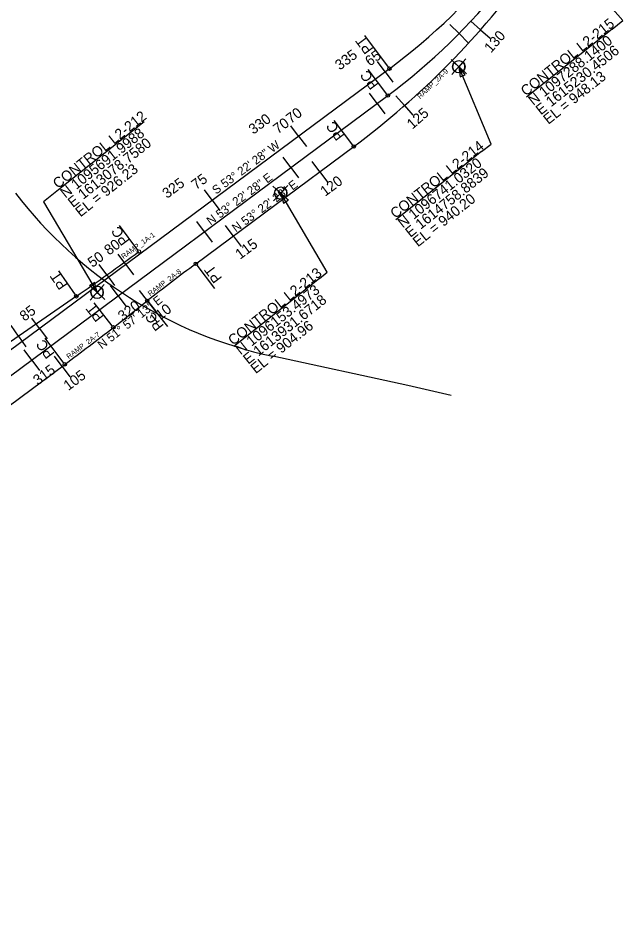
# Model space of a CAD drawing. Extents: x 1603447 to 1622636, y 1083818 to 1103958.
# Drawn here: x 1612712 to 1615521, y 1092765 to 1096967 of the extents above; entities that cross this region are included whole.
import ezdxf

# ---------------------------------------------------------------- set-up
doc = ezdxf.new("R2010")
doc.units = 0
for name, color, linetype in [('Level 1', 7, 'Continuous'), ('RD_HC_Points', 7, 'Continuous'), ('RD_HC_SUR_Bearing_TX400', 7, 'Continuous'), ('RD_HC_SUR_CL400', 7, 'Continuous'), ('RD_HC_SUR_PC_PT_400', 7, 'Continuous'), ('RD_HC_SUR_Tic400', 7, 'Continuous'), ('RD_HC_SUR_TX_Sta400', 7, 'Continuous'), ('RD_SHT_Misc1', 7, 'Continuous'), ('RD_TX_Misc1', 7, 'Continuous')]:
    doc.layers.add(name, color=color, linetype=linetype)

msp = doc.modelspace()

# ---------------------------------------------------------------- linework, layer by layer
at = {"layer": 'RD_HC_Points'}
for p, q in [((1615470.7, 1096915.2), (1615072.9, 1096598.8)), ((1613297.3, 1096484.8), (1612899.4, 1096168.3)), ((1614865, 1096346.2), (1614466.8, 1096029.4)), ((1614111.4, 1095756.1), (1613713.5, 1095439.7))]:
    msp.add_line(p, q, dxfattribs=at)
for points in [[(1615470.7, 1096915.2), (1615521.2, 1096955.3), (1615230.5, 1097288.1)], [(1614865, 1096346.2), (1614908.9, 1096381.1), (1614758.9, 1096741)], [(1612899.4, 1096168.3), (1612830.5, 1096113.5), (1613078.8, 1095692)], [(1614111.4, 1095756.1), (1614148.1, 1095785.3), (1613931.7, 1096153.5)]]:
    msp.add_lwpolyline(points, dxfattribs=at)
for points in [[(1614788.2, 1096703), (1614758.9, 1096741), (1614765.3, 1096693.5)], [(1613965.9, 1096119.8), (1613931.7, 1096153.5), (1613944.5, 1096107.2)], [(1613044.5, 1095725.6), (1613078.8, 1095692), (1613065.9, 1095738.3)]]:
    msp.add_lwpolyline(points, close=True, dxfattribs=at)
at = {"layer": 'RD_HC_SUR_CL400'}
for p, q in [((1614436.6, 1096731.7), (1611265.2, 1094374.2)), ((1609261, 1092765), (1614429, 1096606.7)), ((1613537.5, 1095824.7), (1614270.8, 1096369.8)), ((1612982.5, 1095673.6), (1612407.5, 1095277.3)), ((1613154.3, 1095529.3), (1613311.8, 1095652.5)), ((1614522.1, 1095259), (1613894.5, 1095394.8)), ((1612190.2, 1094808.2), (1612928.5, 1095357.1)), ((1614723.1, 1095212.2), (1614522.1, 1095259))]:
    msp.add_line(p, q, dxfattribs=at)
for centre, radius, start, end in [((1612727.4, 1099031), 2865, 306.6256, 336.8024), ((1612720.8, 1098904.6), 2863.3, 306.6256, 336.8024), ((1612003.8, 1099419.5), 3800, 306.6256, 324.318), ((1614328.1, 1097398.4), 2050, 217.402, 257.7882), ((1607307.2, 1103907.2), 10000, 304.57794, 306.62559), ((1620368.4, 1086635.5), 11450, 126.62559, 128.04643), ((1606097.7, 1104546.3), 11450, 306.62559, 308.04643)]:
    msp.add_arc(centre, radius, start, end, dxfattribs=at)
at = {"layer": 'RD_HC_SUR_PC_PT_400'}
for p, q in [((1614431.8, 1096738.1), (1614321.8, 1096886.1)), ((1614424.2, 1096613.1), (1614338.5, 1096728.5)), ((1614266.1, 1096376.2), (1614180.3, 1096491.6)), ((1613268.3, 1095888.1), (1613182.5, 1096003.5)), ((1613542.3, 1095818.3), (1613623.4, 1095709.3)), ((1612977.9, 1095680.2), (1612900.8, 1095792)), ((1613316.7, 1095646.2), (1613405.3, 1095533)), ((1613149.4, 1095535.6), (1613065.6, 1095642.5)), ((1612923.8, 1095363.5), (1612838, 1095478.9))]:
    msp.add_line(p, q, dxfattribs=at)
for centre in [(1614436.6, 1096731.7), (1614429, 1096606.7), (1614270.8, 1096369.8), (1613273, 1095881.7), (1613537.5, 1095824.7), (1612982.5, 1095673.6), (1613311.8, 1095652.5), (1613154.3, 1095529.3), (1612928.5, 1095357.1)]:
    msp.add_circle(centre, 8, dxfattribs=at)
at = {"layer": 'RD_HC_SUR_Tic400'}
for p, q in [((1614860.1, 1096913.2), (1614815, 1096952.8)), ((1614760.1, 1096894.7), (1614717.3, 1096936.8)), ((1614860.1, 1096913.2), (1614905.2, 1096873.6)), ((1614648.8, 1096905.8), (1614648.8, 1096905.8)), ((1614760.1, 1096894.7), (1614802.8, 1096852.6)), ((1614573.5, 1096840.1), (1614573.5, 1096840.1)), ((1614688.6, 1096824.7), (1614688.6, 1096824.7)), ((1614793.2, 1096838.9), (1614793.2, 1096838.9)), ((1614416.3, 1096716.5), (1614380.5, 1096764.7)), ((1614495.9, 1096777), (1614495.9, 1096777)), ((1614614.8, 1096757.3), (1614614.8, 1096757.3)), ((1614724.3, 1096766.4), (1614724.3, 1096766.4)), ((1614416.3, 1096716.5), (1614452, 1096668.4)), ((1614336, 1096656.9), (1614336, 1096656.9)), ((1614538.7, 1096692.4), (1614538.7, 1096692.4)), ((1614653.5, 1096695.7), (1614653.5, 1096695.7)), ((1614380.2, 1096570.4), (1614344.4, 1096618.6)), ((1614460.3, 1096630.3), (1614460.3, 1096630.3)), ((1614581, 1096627), (1614581, 1096627)), ((1614255.7, 1096597.2), (1614255.7, 1096597.2)), ((1614380.2, 1096570.4), (1614416, 1096522.3)), ((1614506.6, 1096560.1), (1614467.1, 1096605.3)), ((1614175.5, 1096537.6), (1614175.5, 1096537.6)), ((1614506.6, 1096560.1), (1614546.1, 1096515)), ((1614300, 1096510.8), (1614300, 1096510.8)), ((1614430.5, 1096495.3), (1614430.5, 1096495.3)), ((1614015, 1096418.2), (1613979.2, 1096466.4)), ((1614095.2, 1096477.9), (1614095.2, 1096477.9)), ((1614219.7, 1096451.1), (1614219.7, 1096451.1)), ((1614015, 1096418.2), (1614050.8, 1096370.1)), ((1614352.7, 1096432.4), (1614352.7, 1096432.4)), ((1614273.3, 1096371.6), (1614273.3, 1096371.6)), ((1613934.7, 1096358.6), (1613934.7, 1096358.6)), ((1613978.9, 1096272.1), (1613943.1, 1096320.3)), ((1614059.2, 1096331.8), (1614059.2, 1096331.8)), ((1613854.5, 1096298.9), (1613854.5, 1096298.9)), ((1614112.8, 1096252.3), (1614077, 1096300.5)), ((1614193, 1096312), (1614193, 1096312)), ((1613774.2, 1096239.3), (1613774.2, 1096239.3)), ((1613978.9, 1096272.1), (1614014.7, 1096224)), ((1614112.8, 1096252.3), (1614148.6, 1096204.2)), ((1613898.7, 1096212.5), (1613898.7, 1096212.5)), ((1614032.5, 1096192.7), (1614032.5, 1096192.7)), ((1613613.7, 1096119.9), (1613577.9, 1096168.1)), ((1613694, 1096179.6), (1613694, 1096179.6)), ((1613818.4, 1096152.8), (1613818.4, 1096152.8)), ((1613613.7, 1096119.9), (1613649.5, 1096071.8)), ((1613952.3, 1096133), (1613952.3, 1096133)), ((1613738.2, 1096093.2), (1613738.2, 1096093.2)), ((1613872, 1096073.3), (1613872, 1096073.3)), ((1613533.4, 1096060.3), (1613533.4, 1096060.3)), ((1613657.9, 1096033.5), (1613657.9, 1096033.5)), ((1613453.2, 1096000.6), (1613453.2, 1096000.6)), ((1613577.7, 1095973.8), (1613541.9, 1096022)), ((1613711.5, 1095954), (1613675.7, 1096002.2)), ((1613791.8, 1096013.7), (1613791.8, 1096013.7)), ((1613372.9, 1095941), (1613372.9, 1095941)), ((1613577.7, 1095973.8), (1613613.5, 1095925.7)), ((1613711.5, 1095954), (1613747.3, 1095905.9)), ((1613497.4, 1095914.2), (1613497.4, 1095914.2)), ((1613212.4, 1095821.7), (1613176.6, 1095869.8)), ((1613292.7, 1095881.3), (1613292.7, 1095881.3)), ((1613631.2, 1095894.4), (1613631.2, 1095894.4)), ((1613123.9, 1095772.9), (1613089, 1095821.7)), ((1613204.9, 1095831.5), (1613204.9, 1095831.5)), ((1613212.4, 1095821.7), (1613248.2, 1095773.5)), ((1613417.2, 1095854.5), (1613417.2, 1095854.5)), ((1613551, 1095834.7), (1613551, 1095834.7)), ((1613123.9, 1095772.9), (1613158.8, 1095724.1)), ((1613336.9, 1095794.9), (1613336.9, 1095794.9)), ((1613470.9, 1095774.8), (1613470.9, 1095774.8)), ((1613132.2, 1095762), (1613132.2, 1095762)), ((1613256.6, 1095735.2), (1613256.6, 1095735.2)), ((1613042.3, 1095715.2), (1613042.3, 1095715.2)), ((1613051.9, 1095702.3), (1613051.9, 1095702.3)), ((1613176.4, 1095675.6), (1613140.6, 1095723.7)), ((1613312.3, 1095652.9), (1613275.4, 1095700.2)), ((1613391.4, 1095714.2), (1613391.4, 1095714.2)), ((1612960.1, 1095658.2), (1612960.1, 1095658.2)), ((1613176.4, 1095675.6), (1613212.2, 1095627.4)), ((1613312.3, 1095652.9), (1613349.3, 1095605.7)), ((1612971.7, 1095642.7), (1612971.7, 1095642.7)), ((1613096.1, 1095615.9), (1613096.1, 1095615.9)), ((1612811.2, 1095523.4), (1612775.4, 1095571.5)), ((1612877.7, 1095601.4), (1612877.7, 1095601.4)), ((1612891.4, 1095583), (1612891.4, 1095583)), ((1613233.6, 1095591.3), (1613233.6, 1095591.3)), ((1612713.1, 1095487.9), (1612679, 1095537.3)), ((1612795.4, 1095544.7), (1612795.4, 1095544.7)), ((1612811.2, 1095523.4), (1612846.9, 1095475.2)), ((1613015.9, 1095556.2), (1613015.9, 1095556.2)), ((1613154.8, 1095529.7), (1613154.8, 1095529.7)), ((1612713.1, 1095487.9), (1612747.1, 1095438.5)), ((1612935.6, 1095496.6), (1612935.6, 1095496.6)), ((1612730.9, 1095463.7), (1612730.9, 1095463.7)), ((1612855.4, 1095436.9), (1612855.4, 1095436.9)), ((1613075.8, 1095468.4), (1613075.8, 1095468.4)), ((1612775.1, 1095377.3), (1612739.3, 1095425.4)), ((1612916.2, 1095347.9), (1612880.4, 1095396)), ((1612996.3, 1095407.8), (1612996.3, 1095407.8)), ((1612775.1, 1095377.3), (1612810.9, 1095329.1)), ((1612916.2, 1095347.9), (1612952, 1095299.7)), ((1612835.9, 1095288.2), (1612835.9, 1095288.2)), ((1612755.7, 1095228.6), (1612755.7, 1095228.6))]:
    msp.add_line(p, q, dxfattribs=at)
at = {"layer": 'RD_SHT_Misc1'}
for p, q in [((1614722.9, 1096774), (1614794.8, 1096708.1)), ((1614725.9, 1096705.1), (1614791.8, 1096777)), ((1614758.9, 1096741), (1614737.7, 1096760.5)), ((1614739.5, 1096719.8), (1614758.9, 1096741)), ((1614778.3, 1096762.2), (1614758.9, 1096741)), ((1614758.9, 1096741), (1614780.1, 1096721.6)), ((1613895.7, 1096186.4), (1613967.6, 1096120.6)), ((1613898.7, 1096117.6), (1613964.6, 1096189.4)), ((1613931.7, 1096153.5), (1613910.5, 1096172.9)), ((1613912.2, 1096132.3), (1613931.7, 1096153.5)), ((1613951.1, 1096174.7), (1613931.7, 1096153.5)), ((1613931.7, 1096153.5), (1613952.9, 1096134.1)), ((1613042.8, 1095724.9), (1613114.7, 1095659.1)), ((1613045.8, 1095656.1), (1613111.7, 1095727.9)), ((1613078.8, 1095692), (1613057.6, 1095711.4)), ((1613059.3, 1095670.8), (1613078.8, 1095692)), ((1613098.2, 1095713.2), (1613078.8, 1095692)), ((1613078.8, 1095692), (1613100, 1095672.6))]:
    msp.add_line(p, q, dxfattribs=at)
for centre in [(1614758.9, 1096741), (1613931.7, 1096153.5), (1613078.8, 1095692)]:
    msp.add_circle(centre, 28.8, dxfattribs=at)
for centre, start, end in [((1614758.9, 1096741), 137.4919, 227.4919), ((1614758.9, 1096741), 317.4919, 47.4919), ((1613931.7, 1096153.5), 137.4919, 227.4919), ((1613931.7, 1096153.5), 317.4919, 47.4919), ((1613078.8, 1095692), 137.4919, 227.4919), ((1613078.8, 1095692), 317.4919, 47.4919)]:
    msp.add_arc(centre, 28.8, start, end, dxfattribs=at)

# ---------------------------------------------------------------- texts
at = {"layer": 'Level 1'}
for s, rotation, p in [('335', 36.6256, (1614206.2, 1096722.7)), ('65', 36.6256, (1614346, 1096741)), ('125', 41.1949, (1614543.2, 1096448)), ('75', 36.6256, (1613538.8, 1096166.8)), ('325', 36.6256, (1613403.7, 1096126.1)), ('115', 36.6256, (1613743, 1095843.2)), ('85', 36.6256, (1612741.2, 1095555.1)), ('315', 36.6256, (1612803.7, 1095258.1)), ('105', 36.6256, (1612945, 1095232.8))]:
    msp.add_text(s, height=48, rotation=rotation, dxfattribs=at).set_placement(p)
at = {"layer": 'RD_HC_Points'}
for s, p in [('CONTROL L2-215', (1615070.4, 1096601.9)), ('N 1097288.1400', (1615105.3, 1096558.1)), ('E 1615230.4506', (1615140.1, 1096514.3)), ('EL = 948.13', (1615175, 1096470.4)), ('CONTROL L2-212', (1612896.9, 1096171.5)), ('N 1095691.9988', (1612931.8, 1096127.6)), ('E 1613078.7580', (1612966.6, 1096083.8)), ('CONTROL L2-214', (1614464.3, 1096032.6)), ('EL = 926.23', (1613001.5, 1096040)), ('N 1096741.0320', (1614499.2, 1095988.7)), ('E 1614758.8839', (1614534, 1095944.9)), ('EL = 940.20', (1614568.9, 1095901.1)), ('CONTROL L2-213', (1613711.1, 1095442.8)), ('N 1096153.4973', (1613745.9, 1095399)), ('E 1613931.6718', (1613780.8, 1095355.1)), ('EL = 904.96', (1613815.6, 1095311.3))]:
    msp.add_text(s, height=48, rotation=38.4995, dxfattribs=at).set_placement(p)
at = {"layer": 'RD_HC_SUR_Bearing_TX400'}
for s, rotation, p in [('S 53%%d 22\' 28" W', 36.6256, (1613631.4, 1096145.4)), ('N 53%%d 22\' 28" E', 36.6256, (1613606, 1096002.2)), ('N 53%%d 22\' 28" E', 36.6256, (1613723.9, 1095969.4)), ('N 51%%d 57\' 13" E', 38.0464, (1613100.7, 1095426))]:
    msp.add_text(s, height=40, rotation=rotation, dxfattribs=at).set_placement(p)
at = {"layer": 'RD_HC_SUR_PC_PT_400'}
for s, rotation, p in [('PT', 126.6256, (1614363.9, 1096822.8)), ('PC', 126.6256, (1614388.6, 1096657.7)), ('PC', 126.6256, (1614230.5, 1096420.8)), ('PC', 126.6256, (1613232.6, 1095932.6)), ('PT', 124.5779, (1612943.9, 1095726)), ('PT', 126.6256, (1613661.5, 1095757.8)), ('PT', 128.0464, (1613112.7, 1095579.2)), ('PC', 128.0464, (1613391, 1095536.7)), ('PC', 126.6256, (1612883.3, 1095406.5))]:
    msp.add_text(s, height=48, rotation=rotation, dxfattribs=at).set_placement(p)
at = {"layer": 'RD_HC_SUR_TX_Sta400'}
for s, rotation, p in [('130', 48.7339, (1614908.4, 1096802.3)), ('70', 36.6256, (1613978.6, 1096474)), ('330', 36.6256, (1613804.8, 1096424.3)), ('70', 36.6256, (1613918.6, 1096426.4)), ('120', 36.6256, (1614137.9, 1096135.7)), ('80', 36.6256, (1613134, 1095862.2)), ('50', 35.568, (1613056.8, 1095805.4)), ('320', 36.6256, (1613197.6, 1095555.8)), ('110', 38.0429, (1613344.7, 1095539.2))]:
    msp.add_text(s, height=48, rotation=rotation, dxfattribs=at).set_placement(p)
at = {"layer": 'RD_TX_Misc1'}
for s, rotation, p in [('RAMP_2A-9', 43.7351, (1614579.2, 1096589.3)), ('RAMP_1A-1', 36.0654, (1613201.7, 1095845.9)), ('RAMP_2A-8', 37.0717, (1613325.6, 1095673.1)), ('RAMP_2A-7', 36.7727, (1612947.1, 1095380.6))]:
    msp.add_text(s, height=24, rotation=rotation, dxfattribs=at).set_placement(p)

doc.saveas('drawing.dxf')
